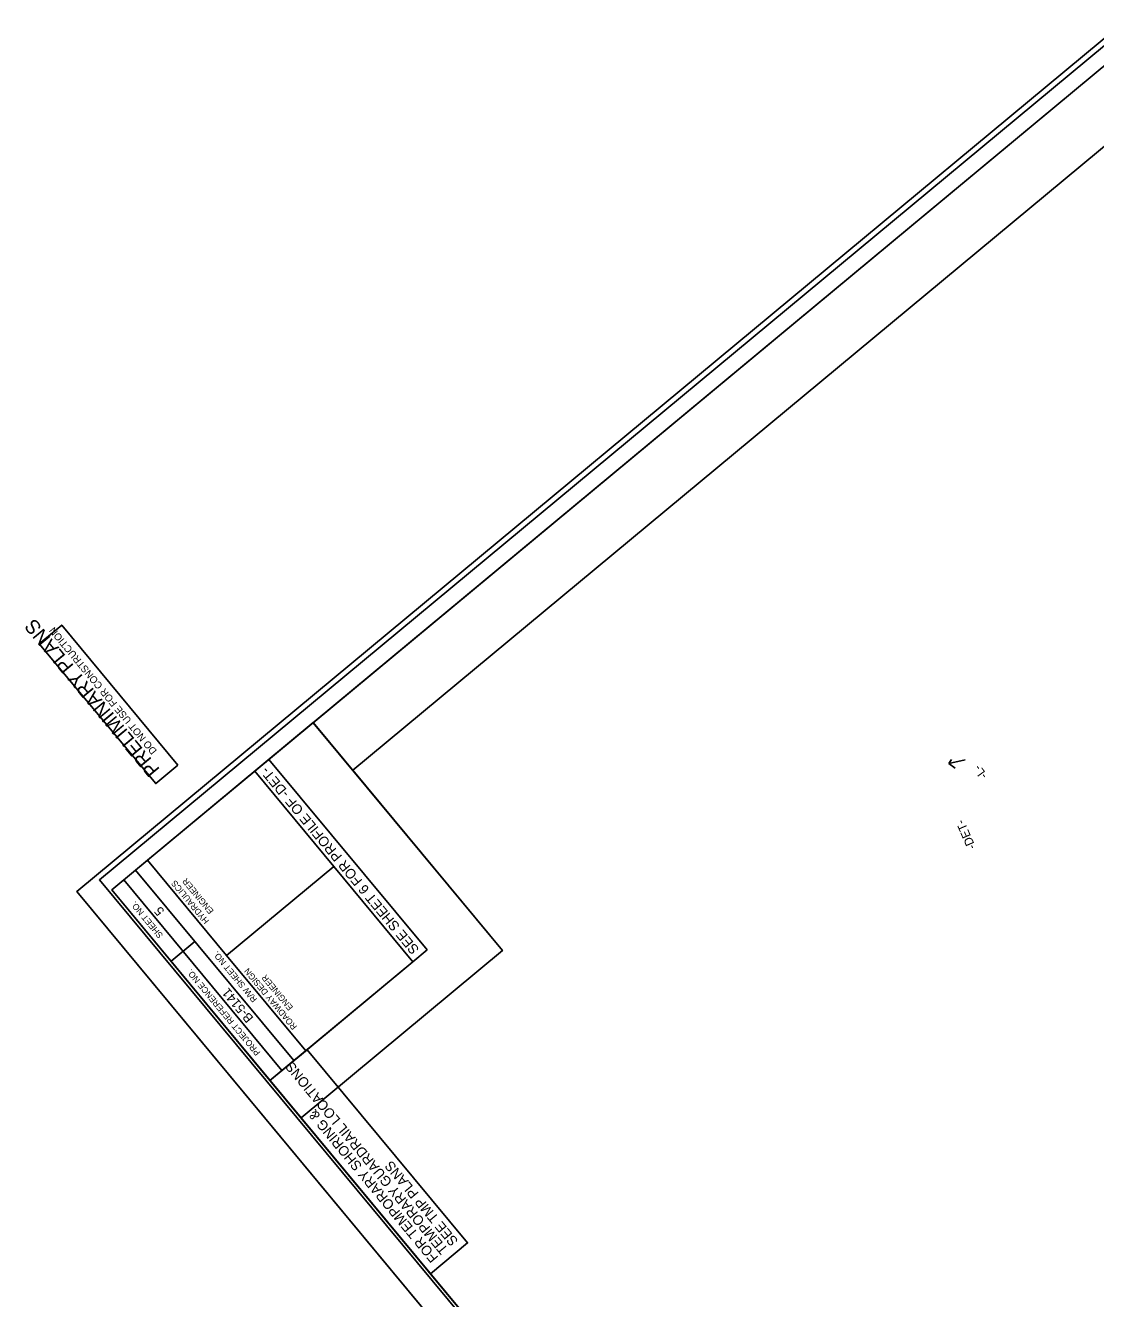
# Model space of a CAD drawing. Extents: x 2597036 to 2598995, y 852197 to 854192.
# Drawn here: x 2597036 to 2597900, y 853163 to 854192 of the extents above; entities that cross this region are included whole.
import ezdxf

# ---------------------------------------------------------------- set-up
doc = ezdxf.new("R2010")
doc.units = 0
for name, color, linetype in [('Default', 7, 'Continuous'), ('Old_Level_1', 7, 'Continuous'), ('Old_Level_2', 7, 'Continuous'), ('Prop Horizontal Alignment Direction Label', 7, 'Continuous'), ('Scratch_Level_6', 7, 'Continuous'), ('Sheet Clip Boundary CELL', 7, 'Continuous'), ('Sheet Cutting Line CELL', 7, 'Continuous'), ('Sheet Data Field CELL', 7, 'Continuous'), ('Sheet Plan CELL', 7, 'Continuous'), ('Sheet Plan Layout CELL', 7, 'Continuous'), ('Sheet Plot Border Inside CELL', 7, 'Continuous'), ('Sheet Plot Border Outside CELL', 7, 'Continuous'), ('Sheet Sticker Preliminary CELL', 7, 'Continuous')]:
    doc.layers.add(name, color=color, linetype=linetype)

msp = doc.modelspace()

# ---------------------------------------------------------------- linework, layer by layer
at = {"layer": 'Default'}
msp.add_lwpolyline([(2597363, 853183.3), (2597233.3, 853339.4), (2597263.3, 853364.3), (2597393, 853208.2)], close=True, dxfattribs=at)
at = {"layer": 'Scratch_Level_6'}
for q in [(2597783.8, 853598.8), (2597794.9, 853598.5), (2597786.8, 853591.8)]:
    msp.add_line((2597781.7, 853595.6), q, dxfattribs=at)
at = {"layer": 'Sheet Clip Boundary CELL'}
msp.add_lwpolyline([(2598839.7, 853048.6), (2597945.3, 854125.7), (2597300.2, 853590), (2597421.1, 853444.4), (2597258.4, 853309.3), (2598031.9, 852377.8)], close=True, dxfattribs=at)
at = {"layer": 'Sheet Cutting Line CELL'}
msp.add_line((2597077.4, 853492.1), (2598152.9, 852196.9), dxfattribs=at)
at = {"layer": 'Sheet Plan CELL'}
for p, q in [((2597360.3, 853444.9), (2597232.5, 853598.8)), ((2597252.6, 853355.5), (2597124.8, 853509.3)), ((2597252.6, 853355.5), (2597124.8, 853509.3)), ((2597198.3, 853440.4), (2597284.8, 853512.3)), ((2597243, 853347.4), (2597115.2, 853501.4)), ((2597153.5, 853435.7), (2597172.7, 853451.7)), ((2597348.8, 853435.3), (2597360.3, 853444.9)), ((2597252.6, 853355.5), (2597262.2, 853363.4))]:
    msp.add_line(p, q, dxfattribs=at)
for points in [[(2597105.5, 853493.4), (2598063.8, 852339.3), (2598871.6, 853010.1), (2597913.3, 854164.1)], [(2598871.6, 853010.1), (2598063.9, 852339.3), (2597233.3, 853339.4), (2597348.8, 853435.3), (2597221, 853589.2), (2597913.3, 854164.1)], [(2597198.3, 853440.4), (2597134.4, 853517.3), (2597221, 853589.2), (2597284.9, 853512.3)], [(2597233.3, 853339.4), (2597105.5, 853493.4), (2597124.8, 853509.3), (2597252.6, 853355.5)], [(2597262.2, 853363.4), (2597198.3, 853440.4), (2597284.9, 853512.3), (2597348.8, 853435.3)]]:
    msp.add_lwpolyline(points, close=True, dxfattribs=at)
at = {"layer": 'Sheet Plan Layout CELL'}
for points in [[(2598063.9, 852339.3), (2598871.6, 853010.1), (2597913.3, 854164.1), (2597268.3, 853628.4), (2597421.1, 853444.4), (2597258.4, 853309.3)], [(2597421.1, 853444.4), (2597268.2, 853628.5), (2597105.5, 853493.4), (2597258.4, 853309.3)]]:
    msp.add_lwpolyline(points, close=True, dxfattribs=at)
at = {"layer": 'Sheet Plot Border Inside CELL'}
msp.add_lwpolyline([(2598971.6, 852893.7), (2597907.3, 854175.3), (2597095.6, 853501.4), (2598160, 852219.7)], close=True, dxfattribs=at)
at = {"layer": 'Sheet Plot Border Outside CELL'}
msp.add_lwpolyline([(2598995.3, 852896.4), (2597919.8, 854191.6), (2597077.4, 853492.1), (2598152.9, 852196.9)], close=True, dxfattribs=at)
at = {"layer": 'Sheet Sticker Preliminary CELL'}
msp.add_lwpolyline([(2597159, 853594.2), (2597141, 853579.2), (2597047, 853692.2), (2597065.1, 853707.3)], close=True, dxfattribs=at)

# ---------------------------------------------------------------- texts
at = {"layer": 'Old_Level_1'}
msp.add_text('SEE SHEET 6 FOR PROFILE OF -DET-', height=8, rotation=129.7067, dxfattribs=at).set_placement((2597354.3, 853445.5))
at = {"layer": 'Old_Level_2'}
for s, p in [('TEMPORARY GUARDRAIL LOCATIONS', (2597377.7, 853203.2)), ('FOR TEMPORARY SHORING &', (2597369.7, 853196.5)), ('SEE TMP PLANS', (2597385.8, 853209.9))]:
    msp.add_text(s, height=8, rotation=129.7067, dxfattribs=at).set_placement(p)
at = {"layer": 'Prop Horizontal Alignment Direction Label'}
for s, rotation, p in [('-L-', 125.6188, (2597813.2, 853585.8)), ('-DET-', 113.4972, (2597803.6, 853527.9))]:
    msp.add_text(s, height=7, rotation=rotation, dxfattribs=at).set_placement(p)
at = {"layer": 'Sheet Data Field CELL'}
for s, p in [('5', (2597148.5, 853476.4)), ('B-5141', (2597220.4, 853390))]:
    msp.add_text(s, height=7.5, rotation=129.7067, dxfattribs=at).set_placement(p)
at = {"layer": 'Sheet Plan CELL'}
for s, p in [('HYDRAULICS', (2597184.5, 853468.5)), ('ENGINEER', (2597188.2, 853476.5)), ('SHEET NO.', (2597147.3, 853456.9)), ('R/W SHEET NO.', (2597223.3, 853405.2)), ('PROJECT REFERENCE NO.', (2597225.9, 853362.1)), ('ROADWAY DESIGN', (2597255.5, 853383)), ('ENGINEER', (2597252.3, 853398.6))]:
    msp.add_text(s, height=5, rotation=129.7067, dxfattribs=at).set_placement(p)
at = {"layer": 'Sheet Sticker Preliminary CELL'}
for s, height, p in [('PRELIMINARY PLANS', 11.52, (2597144.8, 853590.8)), ('DO NOT USE FOR CONSTRUCTION', 5.76, (2597142.3, 853605.8))]:
    msp.add_text(s, height=height, rotation=129.7067, dxfattribs=at).set_placement(p)

doc.saveas('drawing.dxf')
